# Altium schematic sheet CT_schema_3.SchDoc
size 334 x 183 mm
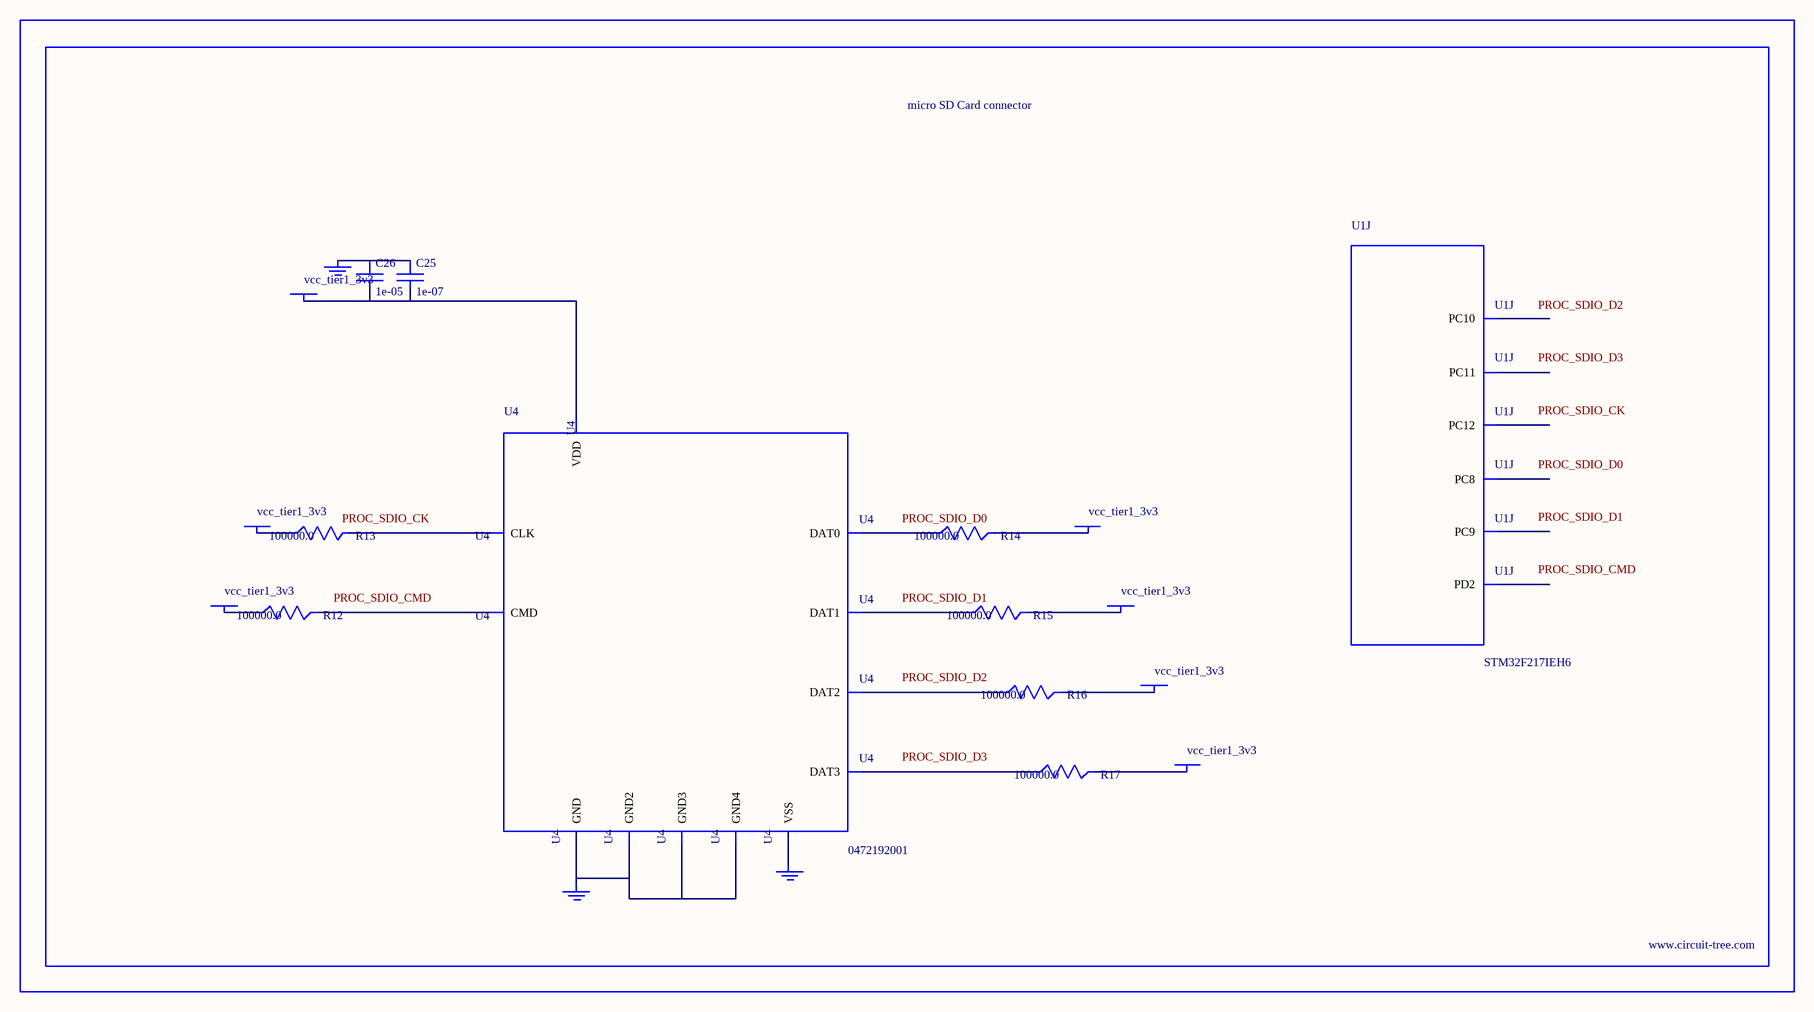
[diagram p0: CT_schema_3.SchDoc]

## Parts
BORDER2  (no value)
C25  1e-07  [C0402]
C26  1e-05  [C0805]
GND_INSTANCE_2_0  (no value)
GND_INSTANCE_2_1  (no value)
GND_INSTANCE_2_2  (no value)
POWER_INSTANCE_2_0  vcc_tier1_3v3
POWER_INSTANCE_2_1  vcc_tier1_3v3
POWER_INSTANCE_2_2  vcc_tier1_3v3
POWER_INSTANCE_2_3  vcc_tier1_3v3
POWER_INSTANCE_2_4  vcc_tier1_3v3
POWER_INSTANCE_2_5  vcc_tier1_3v3
POWER_INSTANCE_2_6  vcc_tier1_3v3
R12  100000.0  [R0603]
R13  100000.0  [R0603]
R14  100000.0  [R0603]
R15  100000.0  [R0603]
R16  100000.0  [R0603]
R17  100000.0  [R0603]
U1  STM32F217IEH6  [UFBGA176_25]  (part J of 14)
U4  0472192001  [MOLEX_47219-2001]

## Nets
NetC25_1: C25.1 C26.1 GND_INSTANCE_2_0.0(GND)
NetC25_2: C25.2 C26.2 POWER_INSTANCE_2_3.0(PWR) U4.4(VDD)
NetGND_INSTANCE_2_1_0: GND_INSTANCE_2_1.0(GND) U4.6(VSS)
NetGND_INSTANCE_2_2_0: GND_INSTANCE_2_2.0(GND) U4.G1(GND) U4.G2(GND2) U4.G3(GND3) U4.G4(GND4)
NetPOWER_INSTANCE_2_0_0: POWER_INSTANCE_2_0.0(PWR) R16.2
NetPOWER_INSTANCE_2_1_0: POWER_INSTANCE_2_1.0(PWR) R17.2
NetPOWER_INSTANCE_2_2_0: POWER_INSTANCE_2_2.0(PWR) R12.1
NetPOWER_INSTANCE_2_4_0: POWER_INSTANCE_2_4.0(PWR) R13.1
NetPOWER_INSTANCE_2_5_0: POWER_INSTANCE_2_5.0(PWR) R14.2
NetPOWER_INSTANCE_2_6_0: POWER_INSTANCE_2_6.0(PWR) R15.2
NetR12_2: R12.2 U4.3(CMD)
NetR13_2: R13.2 U4.5(CLK)
NetR14_1: R14.1 U4.7(DAT0)
NetR15_1: R15.1 U4.8(DAT1)
NetR16_1: R16.1 U4.1(DAT2)
NetR17_1: R17.1 U4.2(DAT3)

Not connected (* = marked no-connect by the designer): U1 A12(PC12) B13(PC11) B14(PC10) D12(PD2) F14(PC9) G14(PC8)

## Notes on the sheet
- Labels drawn without touching a wire or pin: PROC_SDIO_CK, PROC_SDIO_CMD, PROC_SDIO_D0, PROC_SDIO_D1, PROC_SDIO_D2, PROC_SDIO_D3

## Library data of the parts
BORDER2 = BORDER_PAGE2
C25 = C0402C104K3RACTU
C26 = C0805C106K8RACTU
GND_INSTANCE_2_0-GND_INSTANCE_2_2 = GND
POWER_INSTANCE_2_0-POWER_INSTANCE_2_6 = PWR
R12-R17 = RC0603JR-07100KL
